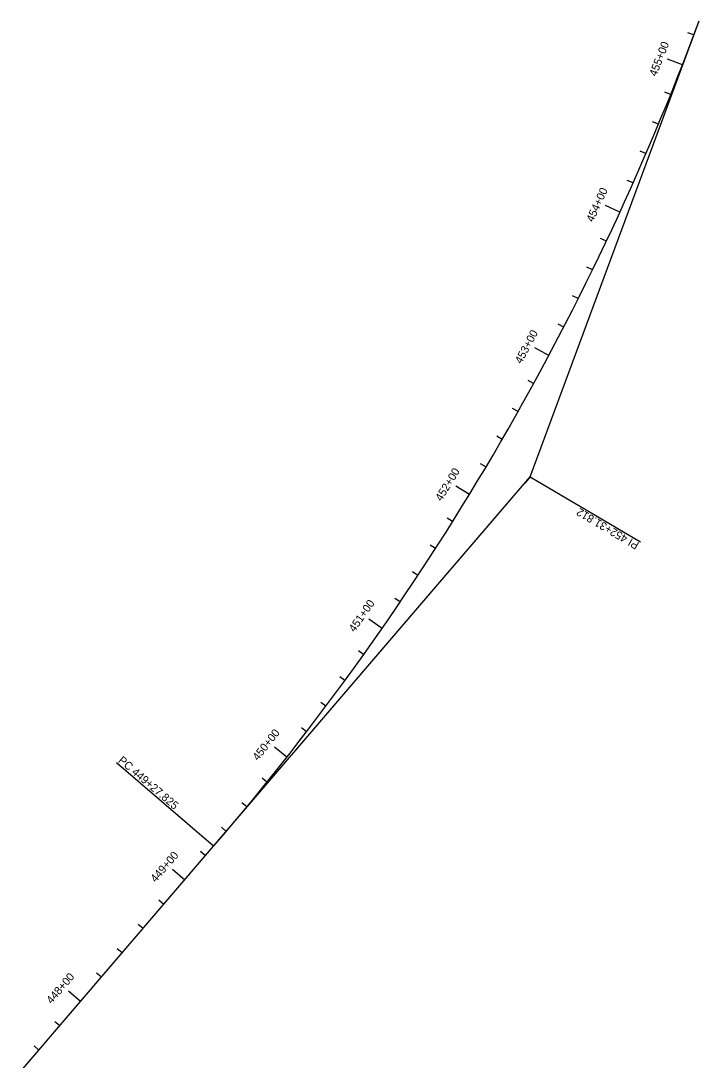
# Model space of a CAD drawing. Extents: x 187748 to 191086, y 249974 to 259749.
# Drawn here: x 188986 to 189411, y 251599 to 252248 of the extents above; entities that cross this region are included whole.
import ezdxf

# ---------------------------------------------------------------- set-up
doc = ezdxf.new("R2010")
doc.units = 0
doc.layers.add('BORDER', color=7, linetype='Continuous')

msp = doc.modelspace()

# ---------------------------------------------------------------- linework, layer by layer
at = {"layer": 'BORDER'}
for p, q in [((189407.21, 252239.37), (189403.47, 252240.78)), ((189400.04, 252220.7), (189390.73, 252224.33)), ((189392.66, 252202.11), (189388.95, 252203.61)), ((189385.05, 252183.61), (189381.36, 252185.15)), ((189377.23, 252165.2), (189373.56, 252166.79)), ((189369.2, 252146.89), (189365.55, 252148.52)), ((189360.95, 252128.67), (189351.86, 252132.85)), ((189352.48, 252110.55), (189348.87, 252112.27)), ((189343.81, 252092.53), (189340.21, 252094.29)), ((189334.92, 252074.62), (189331.34, 252076.41)), ((189325.82, 252056.81), (189322.27, 252058.65)), ((189316.51, 252039.1), (189307.69, 252043.81)), ((189306.99, 252021.51), (189303.49, 252023.44)), ((189297.27, 252004.03), (189293.79, 252006)), ((189287.35, 251986.67), (189283.89, 251988.68)), ((189277.22, 251969.43), (189273.78, 251971.47)), ((189304.85, 251963.18), (189301.6, 251959.38)), ((189304.85, 251963.18), (189306.59, 251967.87)), ((189304.85, 251963.18), (189373.8, 251922.6)), ((189266.88, 251952.3), (189258.35, 251957.52)), ((189256.35, 251935.3), (189252.96, 251937.43)), ((189245.62, 251918.42), (189242.26, 251920.59)), ((189234.69, 251901.68), (189231.35, 251903.88)), ((189223.56, 251885.06), (189220.25, 251887.3)), ((189212.24, 251868.57), (189204.03, 251874.28)), ((189200.73, 251852.22), (189197.47, 251854.54)), ((189189.02, 251836), (189185.79, 251838.36)), ((189177.12, 251819.92), (189173.92, 251822.32)), ((189165.04, 251803.99), (189161.87, 251806.42)), ((189152.77, 251788.19), (189144.91, 251794.38)), ((189106.96, 251732.43), (189046.23, 251784.5)), ((189140.31, 251772.55), (189137.2, 251775.06)), ((189127.67, 251757.05), (189124.59, 251759.59)), ((189114.85, 251741.7), (189111.8, 251744.28)), ((188986.39, 251591.84), (189106.96, 251732.43)), ((189101.87, 251726.49), (189098.83, 251729.09)), ((189088.85, 251711.3), (189081.26, 251717.81)), ((189075.83, 251696.12), (189072.79, 251698.73)), ((189062.81, 251680.94), (189059.77, 251683.54)), ((189049.79, 251665.76), (189046.75, 251668.36)), ((189036.77, 251650.58), (189033.73, 251653.18)), ((189023.75, 251635.4), (189016.16, 251641.91)), ((189010.73, 251620.21), (189007.69, 251622.82)), ((188997.71, 251605.03), (188994.67, 251607.64))]:
    msp.add_line(p, q, dxfattribs=at)
msp.add_lwpolyline([(189106.96, 251732.43), (189304.85, 251963.18), (189410.51, 252248.21)], dxfattribs=at)
msp.add_arc((187816.51, 252839.1), 1700, 319.38387, 339.66039, dxfattribs=at)

# ---------------------------------------------------------------- texts
for s, rotation, p in [('455+00', 68.66813, (189383.65, 252213.05)), ('454+00', 65.29779, (189344.11, 252122.04)), ('453+00', 61.92745, (189299.34, 252033.51)), ('452+00', 58.55711, (189249.37, 251947.65)), ('PI 452+31.812', 149.52214, (189373.36, 251921.86)), ('451+00', 55.18677, (189195.06, 251865.83)), ('450+00', 51.81643, (189134.69, 251785.51)), ('PC 449+27.825', 319.38387, (189046.9, 251785.38)), ('449+00', 49.38387, (189070.73, 251709.47)), ('448+00', 49.38387, (189005.65, 251633.58))]:
    msp.add_text(s, height=5, rotation=rotation, dxfattribs=at).set_placement(p)

doc.saveas('drawing.dxf')
